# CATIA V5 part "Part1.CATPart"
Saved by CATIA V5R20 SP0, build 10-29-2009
Part number: Part1
Bounding box of the stored display mesh (mm): x -79.921 to 79.921, y -80 to 119.816, z 0 to 50
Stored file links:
  C:\Users\Lenovo\Desktop\学习\Part1.CATPart
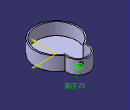
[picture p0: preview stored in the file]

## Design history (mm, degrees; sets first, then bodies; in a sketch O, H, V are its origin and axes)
Body1 (main body)
  Sketch1 on xy-plane, origin (0, 0, 0), H (1, 0, 0), V (0, 1, 0)
    arc A1 centre (0, 0) radius 80 from (-38.7298, 70) to (38.7298, 70) ccw
    arc A2 centre (0, 80) radius 40 from (38.7298, 70) to (-38.7298, 70) ccw
    point P1 (0, 80)
    radius A1 = 80
    radius A2 = 40
    coincidence: P1 V, P1 A1
  Pad1: profile Sketch1, direction (0, 0, 1), length 50
  Shell1: IntOffset 5, Face end face of Pad1, ExtOffset 0
  Sketch2 on start face of Pad1, origin (0, 0, 0), H (1, 0, 0), V (0, -1, 0)
    circle A1 centre (0, -80) radius 12.5
    point P1 (0, -80)
    reference projected arc E1 centre (0, -80) radius 40 from (-38.7298, -70) to (38.7298, -70) ccw from edge [start face of Pad1 | face of Pad1 from Sketch1.A2]
    radius A1 = 12.5
    coincidence: P1 V
    concentricity: A1 E1
  Pocket1: profile Sketch2, direction (0, 0, 1), through (limit type 3)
